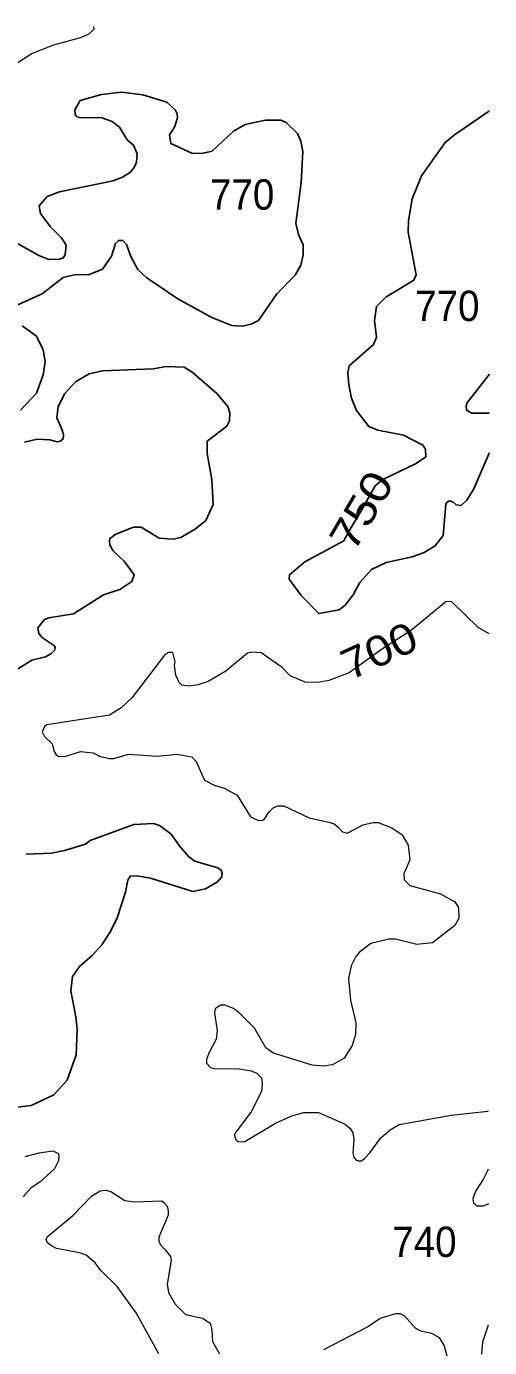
# Model space of a CAD drawing. Extents: x 499.9 to 555.3, y 9281.5 to 9336.8.
# Drawn here: x 552.88 to 555.32, y 9311.1 to 9318.05 of the extents above; entities that cross this region are included whole.
import ezdxf
from ezdxf.enums import TextEntityAlignment as Align

# ---------------------------------------------------------------- set-up
doc = ezdxf.new("R2010")
doc.units = 0
doc.header["$LTSCALE"] = 0.064
doc.layers.add('1', color=7, linetype='Continuous', lineweight=25)
doc.layers.add('2', color=7, linetype='Continuous', lineweight=13)
doc.layers.add('21', color=7, linetype='Continuous')
doc.layers.add('61', color=7, linetype='Continuous')

msp = doc.modelspace()

# ---------------------------------------------------------------- linework, layer by layer
at = {"layer": '1'}
for points in [[(553.0548, 9316.8232), (553.075, 9316.8302), (553.0853, 9316.8466), (553.0901, 9316.8971), (553.0666, 9316.9361), (553.007, 9316.996), (552.956, 9317.0645), (552.9478, 9317.1046), (552.9906, 9317.154), (553.0557, 9317.178), (553.3389, 9317.2355), (553.388, 9317.2553), (553.43, 9317.2822), (553.4502, 9317.3087), (553.4603, 9317.3343), (553.4642, 9317.3778), (553.4454, 9317.423), (553.4119, 9317.451), (553.3711, 9317.5181), (553.3324, 9317.5483), (553.2753, 9317.5694), (553.1679, 9317.5665), (553.1476, 9317.5719), (553.1385, 9317.5847), (553.1371, 9317.6094), (553.1636, 9317.6582), (553.2761, 9317.6907), (553.3827, 9317.7017), (553.4941, 9317.6876), (553.62, 9317.6494), (553.6647, 9317.6098), (553.6749, 9317.5879), (553.676, 9317.5673), (553.661, 9317.519), (553.6353, 9317.4773), (553.6411, 9317.4324), (553.7515, 9317.3817), (553.8037, 9317.3788), (553.8593, 9317.392), (553.9714, 9317.4968), (554.0336, 9317.5316), (554.1392, 9317.555), (554.2213, 9317.5549), (554.2493, 9317.5424), (554.3093, 9317.4857), (554.3254, 9317.4446), (554.3366, 9317.3906), (554.3273, 9317.2274), (554.3004, 9317.0118), (554.3146, 9316.9538), (554.3382, 9316.8996), (554.3384, 9316.8462), (554.3256, 9316.7914), (554.2958, 9316.7396), (554.1995, 9316.6411), (554.1029, 9316.5009), (554.0654, 9316.4809), (554.0188, 9316.4703), (553.9635, 9316.4745), (553.857, 9316.5164), (553.6789, 9316.6152), (553.5156, 9316.7246), (553.4685, 9316.7701), (553.4303, 9316.8383), (553.409, 9316.9012), (553.3895, 9316.9224), (553.3657, 9316.922), (553.3496, 9316.9063), (553.3292, 9316.8398), (553.2814, 9316.7709), (553.2084, 9316.7407), (553.1417, 9316.7435), (553.0749, 9316.7274), (552.964, 9316.6407), (552.8241, 9316.5784)], [(555.3198, 9317.6057), (555.3135, 9317.6014), (555.1345, 9317.4786), (555.0855, 9317.438), (554.9608, 9317.2624), (554.9115, 9317.1415), (554.8924, 9317.0269), (554.8908, 9316.9664), (554.9339, 9316.7414), (554.9207, 9316.7138), (554.8491, 9316.6691), (554.7753, 9316.6262), (554.7244, 9316.5754), (554.7142, 9316.5017), (554.7252, 9316.4141), (554.709, 9316.3744), (554.5798, 9316.2628), (554.5742, 9316.2255), (554.5784, 9316.1622), (554.593, 9316.0918), (554.6186, 9316.0275), (554.684, 9315.9432), (554.7313, 9315.9246), (554.8668, 9315.8968), (554.9685, 9315.8458), (554.983, 9315.8244), (554.984, 9315.7842), (554.9338, 9315.7478), (554.7584, 9315.6641), (554.7174, 9315.6314), (554.6437, 9315.5001), (554.5809, 9315.3938), (554.5521, 9315.3414), (554.3474, 9315.2311), (554.266, 9315.1636), (554.2638, 9315.1393), (554.3284, 9315.054), (554.4201, 9314.9589), (554.5278, 9314.9787), (554.5601, 9315.0032), (554.6014, 9315.0573), (554.6362, 9315.1217), (554.6974, 9315.1905), (554.7746, 9315.2283), (554.9124, 9315.2571), (554.975, 9315.281), (555.0338, 9315.3146), (555.0753, 9315.3694), (555.0899, 9315.5345), (555.0946, 9315.5441), (555.1078, 9315.5515), (555.127, 9315.5465), (555.143, 9315.5309), (555.1708, 9315.5279), (555.1998, 9315.5551), (555.2372, 9315.6161), (555.3173, 9315.8031), (555.3181, 9315.805)], [(552.6171, 9316.9367), (552.7137, 9316.9438), (552.8352, 9316.9062), (552.9475, 9316.8423), (552.9997, 9316.8224), (553.0548, 9316.8232)], [(552.8589, 9316.4725), (552.9333, 9316.4197), (552.9698, 9316.3481), (552.9806, 9316.2829), (552.9694, 9316.2145), (552.9345, 9316.1182), (552.8493, 9316.0296)], [(553.0417, 9315.9893), (553.049, 9316.0492), (553.0844, 9316.1165), (553.1396, 9316.178), (553.2117, 9316.2198), (553.2825, 9316.236), (553.549, 9316.2471), (553.6167, 9316.2581), (553.7113, 9316.2548), (553.7527, 9316.231), (553.883, 9316.1165), (553.9419, 9316.0489), (553.9531, 9316.0146), (553.9502, 9315.9734), (553.9365, 9315.9458), (553.8325, 9315.8654), (553.8325, 9315.8006), (553.8579, 9315.6637), (553.8641, 9315.5329), (553.8252, 9315.4491), (553.7709, 9315.4041), (553.6936, 9315.3586), (553.6517, 9315.3512), (553.5809, 9315.356), (553.5251, 9315.389), (553.4863, 9315.4141), (553.4449, 9315.4142), (553.3512, 9315.3774), (553.3201, 9315.3544), (553.3182, 9315.3414), (553.3201, 9315.3181), (553.3388, 9315.2898), (553.3962, 9315.2348), (553.4489, 9315.1626), (553.4369, 9315.1272), (553.3733, 9315.0857), (553.2877, 9315.0584), (553.1295, 9314.9584), (552.9992, 9314.9372), (552.9767, 9314.9278), (552.9419, 9314.8847), (552.947, 9314.8544), (552.9657, 9314.8318), (553.0293, 9314.7895), (553.0322, 9314.7783), (553.0284, 9314.7642), (553.0106, 9314.7471), (552.9823, 9314.7321), (552.9106, 9314.7134), (552.8064, 9314.6488)], [(555.3183, 9316.0135), (555.2266, 9316.0134), (555.212, 9316.0196), (555.1979, 9316.0306), (555.1956, 9316.048), (555.1996, 9316.0665), (555.3126, 9316.2105), (555.3185, 9316.218)], [(553.0424, 9315.8631), (553.059, 9315.8656), (553.0742, 9315.8778), (553.0772, 9315.9006), (553.068, 9315.93), (553.0417, 9315.9893)], [(552.8718, 9315.8605), (552.9379, 9315.876), (553.0039, 9315.873), (553.0424, 9315.8631)], [(552.8797, 9313.6924), (553.0134, 9313.699), (553.0811, 9313.7117), (553.1923, 9313.7453), (553.2174, 9313.7644), (553.4472, 9313.8484), (553.5506, 9313.8548), (553.5826, 9313.844), (553.6428, 9313.7991), (553.6849, 9313.7381), (553.7359, 9313.6794), (553.7687, 9313.6561), (553.8405, 9313.636), (553.8886, 9313.6213), (553.9062, 9313.6096), (553.912, 9313.592), (553.9109, 9313.5733), (553.8878, 9313.5481), (553.8235, 9313.5099), (553.7568, 9313.4971), (553.534, 9313.5666), (553.4624, 9313.5795), (553.4282, 9313.5772), (553.4155, 9313.5571), (553.4025, 9313.4936), (553.3583, 9313.3575)], [(553.3583, 9313.3575), (553.3246, 9313.2868), (553.2784, 9313.2168), (553.2269, 9313.1604), (553.1613, 9313.1027), (553.1243, 9313.0495)], [(553.1243, 9313.0495), (553.1147, 9312.9748), (553.1416, 9312.8379), (553.1479, 9312.771), (553.143, 9312.6375), (553.0953, 9312.5038), (553.0259, 9312.426), (552.906, 9312.3701), (552.836, 9312.3621), (552.7015, 9312.3654), (552.4767, 9312.4127)]]:
    msp.add_lwpolyline(points, dxfattribs=at)
at = {"layer": '2'}
for points in [[(553.2352, 9318.0486), (553.2364, 9318.0337), (553.2115, 9318.009), (553.1719, 9317.9906), (553.0231, 9317.9497), (552.9122, 9317.9051), (552.7698, 9317.8132)], [(555.3172, 9314.8522), (555.2596, 9314.8852), (555.1206, 9315.0211), (555.092, 9315.023), (554.9088, 9314.8708), (554.7513, 9314.7702), (554.5804, 9314.6466), (554.473, 9314.6062), (554.4148, 9314.5966), (554.3482, 9314.5978), (554.27, 9314.6318), (554.227, 9314.6745), (554.1176, 9314.753), (554.068, 9314.7556), (554.0452, 9314.7504), (553.9309, 9314.6556), (553.8387, 9314.6014), (553.7858, 9314.5836), (553.7376, 9314.5776), (553.6988, 9314.5821), (553.6857, 9314.5958), (553.6687, 9314.6357), (553.6607, 9314.6865), (553.6647, 9314.7056), (553.6513, 9314.7537), (553.6286, 9314.7542), (553.609, 9314.7407), (553.4386, 9314.5181), (553.381, 9314.4635), (553.3182, 9314.4249), (552.988, 9314.3738), (552.9767, 9314.3646), (552.9639, 9314.3371), (552.9762, 9314.3118), (553.0162, 9314.2728), (553.0279, 9314.2332), (553.0374, 9314.2155), (553.0519, 9314.2067), (553.0888, 9314.2087), (553.1657, 9314.2335), (553.2325, 9314.2259), (553.2666, 9314.2081), (553.3173, 9314.1956), (553.3412, 9314.1959), (553.4193, 9314.2193), (553.5694, 9314.2084), (553.6739, 9314.2193), (553.752, 9314.2051), (553.7749, 9314.181), (553.8183, 9314.0828), (553.8706, 9314.0555), (553.9232, 9314.0403), (553.9912, 9314.0038), (554.0618, 9313.8888), (554.099, 9313.8728), (554.12, 9313.8708), (554.1331, 9313.8757), (554.1599, 9313.9163), (554.1809, 9313.9376), (554.2053, 9313.947), (554.2366, 9313.9472), (554.3703, 9313.8836), (554.4728, 9313.8623), (554.501, 9313.8532), (554.5222, 9313.8345), (554.5459, 9313.8104), (554.5708, 9313.8032), (554.6543, 9313.8471), (554.7052, 9313.8597), (554.7325, 9313.8589), (554.8045, 9313.8318), (554.8572, 9313.7959), (554.891, 9313.74), (554.9001, 9313.6631), (554.8689, 9313.5898), (554.8695, 9313.5573), (554.8995, 9313.5285), (555.0606, 9313.4837), (555.1373, 9313.4426), (555.1554, 9313.4123), (555.1571, 9313.356), (555.1363, 9313.3174), (555.0186, 9313.2267), (554.9376, 9313.2184), (554.8239, 9313.245), (554.7898, 9313.2451), (554.6953, 9313.2224), (554.635, 9313.1774), (554.6158, 9313.1552), (554.5907, 9313.1048), (554.5771, 9313.0383), (554.5882, 9312.9246), (554.6153, 9312.8054), (554.6144, 9312.7445), (554.597, 9312.6868)], [(554.1818, 9312.6458), (554.1421, 9312.6746), (554.0826, 9312.7784), (554.0001, 9312.8605), (553.9711, 9312.8815), (553.9253, 9312.8982), (553.9035, 9312.898), (553.8747, 9312.8788), (553.8707, 9312.857), (553.8862, 9312.7654), (553.88, 9312.7192), (553.8413, 9312.6468), (553.8293, 9312.6119), (553.8297, 9312.5929), (553.851, 9312.5711), (553.8738, 9312.5655), (554.001, 9312.5641), (554.064, 9312.5531), (554.0948, 9312.5402), (554.1189, 9312.5161), (554.1233, 9312.4839), (554.1181, 9312.4438), (554.0643, 9312.3375), (553.9835, 9312.2308), (553.976, 9312.2176), (553.9777, 9312.2027), (553.985, 9312.1906), (553.9969, 9312.1817), (554.0144, 9312.1792), (554.0317, 9312.1815), (554.193, 9312.2773), (554.2786, 9312.3161), (554.3424, 9312.3334), (554.4189, 9312.3333), (554.5589, 9312.2716), (554.5863, 9312.2492), (554.5992, 9312.2266), (554.6042, 9312.1918), (554.5996, 9312.1193), (554.6052, 9312.098), (554.6158, 9312.0851), (554.6286, 9312.0793), (554.6441, 9312.079), (554.6609, 9312.0917), (554.6885, 9312.1214), (554.748, 9312.2002), (554.7971, 9312.2432), (554.843, 9312.2712), (555.1168, 9312.3204), (555.311, 9312.3414), (555.3149, 9312.3418)], [(554.597, 9312.6868), (554.5542, 9312.62), (554.4928, 9312.585), (554.4451, 9312.5785), (554.3862, 9312.5833), (554.1818, 9312.6458)], [(552.8746, 9312.1026), (552.9491, 9312.122), (553.0207, 9312.1324), (553.0489, 9312.1185), (553.0517, 9312.1099), (553.0501, 9312.0793), (553.0299, 9312.0375), (552.9536, 9311.9698), (552.9039, 9311.9349), (552.865, 9311.8897)], [(555.3144, 9311.8527), (555.3077, 9311.8499), (555.2858, 9311.8409), (555.2537, 9311.8403), (555.2364, 9311.8546), (555.2331, 9311.8832), (555.2461, 9311.9163), (555.2864, 9311.9803), (555.3062, 9312.0215), (555.3146, 9312.0374)], [(553.5776, 9311.0637), (553.4588, 9311.2798), (553.3585, 9311.4176), (553.2753, 9311.5011), (553.2428, 9311.5428), (553.1956, 9311.5827), (553.1606, 9311.5957), (553.0398, 9311.6189), (553.0126, 9311.6321), (552.9915, 9311.6488), (552.9859, 9311.6665), (552.9902, 9311.6805), (553.1256, 9311.7923), (553.2234, 9311.8945), (553.269, 9311.9224), (553.2988, 9311.9249), (553.3262, 9311.9178), (553.4002, 9311.8702), (553.4527, 9311.8638), (553.5935, 9311.8686), (553.6054, 9311.8599), (553.6221, 9311.8413), (553.6283, 9311.8161), (553.6284, 9311.7945), (553.5783, 9311.6787), (553.5777, 9311.6584), (553.5857, 9311.6389), (553.6142, 9311.6092), (553.6397, 9311.577), (553.6441, 9311.5551), (553.6227, 9311.4311), (553.629, 9311.386), (553.6641, 9311.3254), (553.7188, 9311.2709), (553.8092, 9311.2512), (553.8479, 9311.2254), (553.8575, 9311.1898), (553.8612, 9311.1285), (553.8982, 9311.0633)], [(554.4473, 9311.086), (554.6765, 9311.207), (554.7444, 9311.2525), (554.8254, 9311.2764), (554.8494, 9311.2765), (554.8715, 9311.2633), (554.9289, 9311.1995), (554.9576, 9311.1859), (555.0132, 9311.173), (555.0549, 9311.15), (555.0803, 9311.1056), (555.1241, 9310.9394)], [(555.2791, 9311.0617), (555.2843, 9311.1279), (555.3138, 9311.2174)]]:
    msp.add_lwpolyline(points, dxfattribs=at)

# ---------------------------------------------------------------- texts
at = {"layer": '21', "width": 0.95}
for s, p in [('770', (553.8474, 9317.084)), ('770', (554.9277, 9316.4979)), ('740', (554.807, 9311.5734))]:
    msp.add_text(s, height=0.16, dxfattribs=at).set_placement(p)
at = {"layer": '61'}
for s, rotation, width, p in [('750', 59.657, 1.2, (554.714, 9315.4618)), ('700', 24.633, 1.15, (554.7714, 9314.6914))]:
    msp.add_text(s, height=0.16, rotation=rotation, dxfattribs=dict(at, width=width)).set_placement(p, align=Align.CENTER)

doc.saveas('drawing.dxf')
